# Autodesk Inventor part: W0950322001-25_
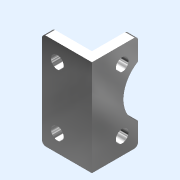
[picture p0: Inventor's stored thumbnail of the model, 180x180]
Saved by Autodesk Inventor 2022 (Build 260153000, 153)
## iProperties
Part Number: W0950322001-25_
Material: Generico
Catalog Web Link: www.cadenas.de
Description: FOOT - MODEL A_-
Vendor: METALWORK
Document SubType Name: Modeling
Designer: partserver
Manufacturer: METALWORK
Mass: 9.83087 g
Surface Area: 53.0709 cm^2
Volume: 9.83087 cm^3
Density: 1 g/cm^3
Appearance: Alluminio - Piatto
Category: PARTsolutions
Company: METALWORK
PSOL_IDENT_0: {$CADENAS_DATA\23d-libs\metalwork\actuators\parts\foot.prj},176 {VTYP=3D},{NB=W0950322001-25_},{LINA=
PSOL_IDENT_1: W0950322001},{NN=FOOT - MODEL A_},{DATE=18.06.2021 08:06:10},{GEOMDATE=02.08.2018 11:04:45},{VERSION=
PSOL_IDENT_2: },{LINEID=110},{WBVAR=},{WBNUMERIC=}  {NB=W0950322001-25_},{LINA=W0950322001},{KT=DUMMY},{IDNR=},{CO
PSOL_IDENT_3: DE=W0950322001},{VER=25},{V1=2},{DI=32},{A=50},{B=26.0},{C=32},{D=18.000},{XS=0.000},{AB=0.000},{AH=
PSOL_IDENT_4: 0.000},{AO=0.000},{AT=0.000},{AU=0.000},{NH=0.000},{TR=0.000},{US=0.000},{R=0.000},{E=6.6},{XA=0.000
PSOL_IDENT_5: },{SA=0.000},{H=31.9},{N=74.5},{N1=92.5},{S=5},{WG=76},{R1=15.500},{BH=24.000},{ND=6.000},{TG=32.250
PSOL_IDENT_6: },{DH=6.600},{SL=16.000},{UH=0.000},{H1=0.000},{H2=0.000}
NB: W0950322001-25_
NN: FOOT - MODEL A_
NBSYN: $CODE.-$VER._
LINA: W0950322001
CATALOG: Metalwork
CODE: W0950322001
VER: 25
V1: 2
DI: 32
A: 50
B: 26
C: 32
D: 18
XS: 0
AB: 0
AH: 0
AO: 0
AT: 0
AU: 0
NH: 0
TR: 0
US: 0
R: 0
E: 6.6
XA: 0
SA: 0
H: 31.9
N: 74.5
N1: 92.5
S: 5
WG: 76
R1: 15.5
BH: 24
ND: 6
TG: 32.25
DH: 6.6
SL: 16
UH: 0
H1: 0
H2: 0
SUPPLIER: METALWORK
ARTICLENO: W0950322001-25_
BOMINFO: W0950322001
CREATOR: CADENAS GmbH
Title: W0950322001
Author: Cadenas PARTsolutions
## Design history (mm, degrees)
sketch "Sketch_1"
  geometry: L1 (0, -7.9)-(0, -31.9); L2 (0, -31.9)-(26, -31.9); L3 (26, -31.9)-(26, -26.9); L4 (26, -26.9)-(5, -26.9); L5 (5, -26.9)-(5, -7.9); L6 (5, -7.9)-(0, -7.9)
  constraints: 12 end point
extrude "Extrusion1" join sketch "Sketch_1" stored distance "d0" = 50; taper "d1" = 0 deg
sketch "Sketch_2"
  geometry: C1 r 15.5 at (0, 0); 1 further point
  constraints: 1 centre point
extrude "Extrusion2" cut sketch "Sketch_2" distance "d2" = 5; taper "d3" = 0 deg
sketch "Sketch_3"
  geometry: C1 r 3.3 at (-18, -16); 1 further point
  constraints: 1 centre point
extrude "Extrusion3" cut sketch "Sketch_3" distance "d4" = 31.9; taper "d5" = 0 deg
sketch "Sketch_4"
  geometry: C1 r 3.3 at (-18, 16); 1 further point
  constraints: 1 centre point
extrude "Extrusion4" cut sketch "Sketch_4" distance "d6" = 31.9; taper "d7" = 0 deg
sketch "Sketch5"
  geometry: 1 further point
hole "Hole1" sketch "Sketch5" at (8.875, 15.775) diameter "d8" = 6.6; stored, may be unused: countersink angle "d12" = 90 deg, drill point angle "d14" = 0 deg; dims "d9" = 6, "d10" = 4, "d11" = 2, "d13" = 5
sketch "Sketch6"
  geometry: 1 further point
hole "Hole2" sketch "Sketch6" at (41.125, 15.775) diameter "d15" = 6.6; stored, may be unused: countersink angle "d19" = 90 deg, drill point angle "d21" = 0 deg; dims "d16" = 6, "d17" = 4, "d18" = 2, "d20" = 5
sketch "Sketch_9"
  geometry: L1 (-17.9, 30)-(-17.9, 25); L2 (-17.9, 25)-(-9.9, 25); L3 (-7.9, 23)-(-7.9, -23); L4 (-9.9, -25)-(-17.9, -25); L5 (-17.9, -25)-(-17.9, -30); L6 (-17.9, -30)-(-2.9, -30); L7 (-2.9, -30)-(-2.9, 30); L8 (-2.9, 30)-(-17.9, 30); A1 r 2 centre (-9.9, 23) between (-7.9, 23) and (-9.9, 25); A2 r 2 centre (-9.9, -23) between (-9.9, -25) and (-7.9, -23)
  constraints: 16 end point, 4 point on circle, 2 centre point
extrude "Extrusion5" cut sketch "Sketch_9" distance "d22" = 5; taper "d23" = 0 deg
sketch "Sketch_10"
  geometry: L1 (-16, 30)-(-31, 30); L2 (-31, 30)-(-31, -30); L3 (-31, -30)-(-16, -30); L4 (-16, -30)-(-16, -25); L5 (-16, -25)-(-24, -25); L6 (-26, -23)-(-26, 23); L7 (-24, 25)-(-16, 25); L8 (-16, 25)-(-16, 30); A1 r 2 centre (-24, -23) between (-26, -23) and (-24, -25); A2 r 2 centre (-24, 23) between (-24, 25) and (-26, 23)
  constraints: 16 end point, 4 point on circle, 2 centre point
extrude "Extrusion6" cut sketch "Sketch_10" distance "d24" = 31.9; taper "d25" = 0 deg
node "body_XY"
node "body_YZ"
node "body_ZX"
node "body_X"
node "body_Y"
node "body_Z"
node "body_Center"
node "screws_1_XY"
node "screws_1_YZ"
node "screws_1_ZX"
node "screws_1_X"
node "screws_1_Y"
node "screws_1_Z"
node "screws_1_Center"
node "screws_2_XY"
node "screws_2_YZ"
node "screws_2_ZX"
node "screws_2_X"
node "screws_2_Y"
node "screws_2_Z"
node "screws_2_Center"
body "Solid1"
other parameters: "d26" = 0, "d27" = 0, "d28" = 0
